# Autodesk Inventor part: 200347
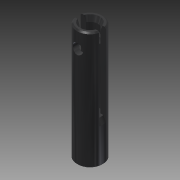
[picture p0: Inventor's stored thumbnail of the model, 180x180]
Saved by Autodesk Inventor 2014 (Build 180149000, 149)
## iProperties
Created: 2007-10
Part Number: 200347
Document SubType Name: Modeling
Designer: TH
Density: 1.425 g/cm^3
Mass: 22.9703 g
Surface Area: 90.2675 cm^2
Volume: 16.1195 cm^3
Material: Acetal Resin, Black
Description: BALL SCREW SLEEVE
Appearance: Rubber - Black - Version 1.1
Component Category: Lower Component
Author: TH
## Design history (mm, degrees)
sketch "Sketch1"
  geometry: C1 r 10 at (0, 0); 1 further point
  constraints: 1 centre point, 1 coincident
  dimensions: "d0" = 20 diameter of C1
extrude "Extrusion1" new body sketch "Sketch1" stored distance "d1" = 90; taper "d2" = 0 deg
sketch "Sketch2"
  geometry: L1 (-10, -2.5)-(10, -2.5); L2 (10, -2.5)-(10, 2.5); L3 (10, 2.5)-(-10, 2.5); L4 (-10, 2.5)-(-10, -2.5); C1 r 6 at (0, 0); 3 further points
  constraints: 8 end point, 2 midpoint, 2 parallel, 1 centre point, 1 coincident, 1 horizontal, 1 perpendicular
  dimensions: "d3" = 12 diameter of C1; "d4" = 5 distance of L3.end L1.start; "d5" = 2.5 distance from line of point (0, 0) L3 (= 0.5 x d4); "d6" = 20 distance of L2.end L3.end; "d7" = 10 distance from line of point (0, 0) L4
extrude "Extrusion2" cut sketch "Sketch2" distance "d8" = 59; taper "d9" = 0 deg
chamfer "Chamfer1" distance "d10" = 1; stored, may be unused: second distance "d11" = 2, angle "d12" = 45 deg
chamfer "Chamfer2" distance "d13" = 1.5; stored, may be unused: second distance "d14" = 4, angle "d15" = 45 deg
chamfer "Chamfer3" distance "d16" = 1.5; stored, may be unused: second distance "d17" = 4, angle "d18" = 45 deg
chamfer "Chamfer4" distance "d19" = 4; stored, may be unused: second distance "d20" = 2, angle "d21" = 45 deg
chamfer "Chamfer5" distance "d22" = 4; stored, may be unused: second distance "d23" = 2, angle "d24" = 45 deg
chamfer "Chamfer6" distance "d25" = 1; stored, may be unused: second distance "d26" = 2, angle "d27" = 45 deg
sketch "Sketch3"
  geometry: C1 r 9 at (0, 0) reference
hole "Hole1" sketch "Sketch3" at (0, 0) diameter "d28" = 10.106; stored, may be unused: countersink angle "d32" = 90 deg, drill point angle "d34" = 0 deg; dims "d29" = 6, "d30" = 4, "d31" = 2, "d33" = 45
sketch "Sketch4"
  geometry: L1 (0, -10)-(0, 60) reference; L2 (-8.646, 45)-(8.646, 45) reference; C1 r 3.95 at (0, 32.297); 1 further point
  constraints: 1 centre point, 1 point on line
  dimensions: "d35" = 12.703 distance from line of L2 C1.centre; "d36" = 7.9 diameter of C1
extrude "Extrusion3" cut sketch "Sketch4" stored distance "d37" = 59; taper "d38" = 0 deg
workpoint "Work Point1"
  workaxis "Work Axis1"
body "Solid1"
other parameters: "sa_eq_min" = 2183.89, "sa_eq_max" = 1388870, "sa_pmax_min" = -31831.2, "sa_pmax_max" = 741244, "sa_pmin_min" = -1475480, "sa_pmin_max" = 106792, "sa_d_min" = 0.00003, "sa_d_max" = 0.01025, "d67" = -137336, "d68" = -4973.8, "d69" = 11076.2, "d70" = 25345.7, "d71" = 0, "d72" = 25077, "d74" = 0, "d75" = -446103, "d76" = 7282, "d77" = 0, "d78" = -446589, "d80" = 0.04817
